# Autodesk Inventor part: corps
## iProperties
Shininess: 25.0
Length Units: 11269
Angle Units: 11279
Time Units: 11290
Mass Units: 11283
Length Display Precision: 3
Angle Display Precision: 2
Compacted: True
Created: 2003-02
Part Number: corps
Material: Acier doux
Document SubType Name: Modélisation
Designer: robert
Density: 7.86 g/cm^3
Density: 0.0
Volumn: 0.0
Area: 0.0
PropertySet Name: Model Information
Control State: 0
Master: False
Checked Out: False
Author: robert
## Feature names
1. Extrusion1
2. Coque1
3. Extrusion6
4. Extrusion3
5. Extrusion4
6. Extrusion5
7. Révolution1 [Revolution]
8. Perçage1 [Hole]
9. Extrusion7
10. Perçage2 [Hole]
11. Extrusion8
12. Perçage3 [Hole]
13. Perçage4 [Hole]
14. Congé1 [Fillet]
15. Extrusion9
16. Extrusion10
17. Extrusion11
18. Extrusion12
19. Extrusion13
20. Extrusion14
21. Perçage5 [Hole]
22. Congé2 [Fillet]
23. Extrusion15
24. Extrusion16
25. Extrusion17
26. Extrusion18
27. Perçage6 [Hole]
28. Perçage7 [Hole]
29. Congé3 [Fillet]
30. Congé4 [Fillet]
31. Congé5 [Fillet]
32. Congé6 [Fillet]
33. Congé7 [Fillet]
34. Congé8 [Fillet]
35. Congé9 [Fillet]
36. Congé10 [Fillet]
37. Congé11 [Fillet]
38. Congé12 [Fillet]
39. Congé13 [Fillet]
40. Congé14 [Fillet]
